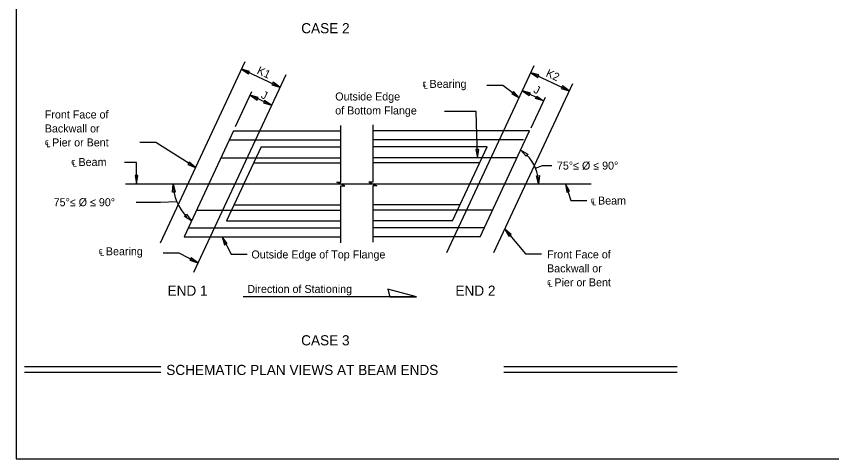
# Model space of a CAD drawing. Extents: x 120790.7 to 120844.8, y 120612.1 to 120653.6.
# Drawn here: x 120790.7 to 120806.1, y 120630.85 to 120639.21 of the extents above; entities that cross this region are included whole.
import ezdxf

# ---------------------------------------------------------------- set-up
doc = ezdxf.new("R2010")
doc.units = 0
for name, color, linetype in [('ActivePts-ConstElements', 7, 'Continuous'), ('AdhocPoint_dp', 7, 'Continuous'), ('Border', 7, 'Continuous'), ('Patterning', 7, 'Continuous'), ('PlotBorder_dp', 7, 'Continuous'), ('TextMisc', 7, 'Continuous')]:
    doc.layers.add(name, color=color, linetype=linetype)

# ---------------------------------------------------------------- blocks, each defined once
blk = doc.blocks.new('Terminator-Arrow')
at = {"layer": 'PlotBorder_dp'}
blk.add_lwpolyline([(0, 0), (-0.00041, 0.000069), (-0.00041, -0.000069)], close=True, dxfattribs=at)

msp = doc.modelspace()

# ---------------------------------------------------------------- linework, layer by layer
at = {"layer": 'ActivePts-ConstElements'}
msp.add_lwpolyline([(120790.703, 120630.851), (120821.491, 120630.851), (120821.491, 120650.31), (120790.703, 120650.31)], close=True, dxfattribs=at)
at = {"layer": 'AdhocPoint_dp'}
for p, q in [((120794.803, 120637.044), (120793.871, 120635.044)), ((120794.803, 120637.044), (120796.83, 120637.044)), ((120800.393, 120637.044), (120797.434, 120637.044)), ((120799.461, 120635.044), (120800.393, 120637.044)), ((120795.324, 120636.742), (120794.673, 120635.346)), ((120795.324, 120636.742), (120796.83, 120636.742)), ((120799.591, 120636.742), (120797.434, 120636.742)), ((120798.94, 120635.346), (120799.591, 120636.742)), ((120795.183, 120636.439), (120796.83, 120636.439)), ((120799.449, 120636.439), (120797.434, 120636.439)), ((120794.815, 120635.649), (120796.83, 120635.649)), ((120799.081, 120635.649), (120797.434, 120635.649)), ((120794.673, 120635.346), (120796.83, 120635.346)), ((120798.94, 120635.346), (120797.434, 120635.346)), ((120793.871, 120635.044), (120796.83, 120635.044)), ((120799.461, 120635.044), (120797.434, 120635.044))]:
    msp.add_line(p, q, dxfattribs=at)
at = {"layer": 'Border'}
for p, q in [((120794.724, 120636.874), (120796.83, 120636.874)), ((120800.277, 120636.874), (120797.434, 120636.874)), ((120794.568, 120636.539), (120796.83, 120636.539)), ((120800.158, 120636.539), (120797.434, 120636.539)), ((120794.106, 120635.549), (120796.83, 120635.549)), ((120799.696, 120635.549), (120797.434, 120635.549)), ((120793.95, 120635.214), (120796.83, 120635.214)), ((120799.54, 120635.214), (120797.434, 120635.214))]:
    msp.add_line(p, q, dxfattribs=at)
at = {"layer": 'Patterning'}
msp.add_lwpolyline([(120797.719, 120634.055), (120797.754, 120633.911), (120798.261, 120633.911)], close=True, dxfattribs=at)
at = {"layer": 'PlotBorder_dp'}
for p, q in [((120795.68, 120637.874), (120794.954, 120638.213)), ((120795.68, 120637.874), (120794.954, 120638.213)), ((120801.143, 120637.805), (120800.416, 120638.144)), ((120801.143, 120637.805), (120800.416, 120638.144)), ((120799.888, 120637.905), (120799.586, 120637.905)), ((120799.888, 120637.905), (120799.586, 120637.905)), ((120800.196, 120637.673), (120799.888, 120637.905)), ((120800.196, 120637.673), (120799.888, 120637.905)), ((120800.659, 120637.614), (120800.257, 120637.802)), ((120800.659, 120637.614), (120800.257, 120637.802)), ((120794.843, 120637.129), (120795.15, 120637.788)), ((120794.843, 120637.129), (120795.15, 120637.788)), ((120795.521, 120637.532), (120795.118, 120637.719)), ((120795.521, 120637.532), (120795.118, 120637.719)), ((120800.421, 120637.104), (120800.691, 120637.683)), ((120800.421, 120637.104), (120800.691, 120637.683)), ((120799.383, 120637.412), (120798.784, 120637.412)), ((120799.383, 120637.412), (120798.784, 120637.412)), ((120799.412, 120636.539), (120799.383, 120637.412)), ((120799.412, 120636.539), (120799.383, 120637.412)), ((120793.336, 120636.826), (120793.034, 120636.826)), ((120793.336, 120636.826), (120793.034, 120636.826)), ((120794.086, 120636.351), (120793.336, 120636.826)), ((120794.086, 120636.351), (120793.336, 120636.826)), ((120792.971, 120636.446), (120792.748, 120636.446)), ((120792.971, 120636.446), (120792.748, 120636.446)), ((120792.973, 120636.044), (120792.97, 120636.446)), ((120792.973, 120636.044), (120792.97, 120636.446)), ((120801.073, 120636.044), (120801.174, 120635.73)), ((120801.073, 120636.044), (120801.174, 120635.73)), ((120801.174, 120635.73), (120801.476, 120635.73)), ((120801.174, 120635.73), (120801.476, 120635.73)), ((120799.923, 120635.19), (120800.316, 120634.723)), ((120799.923, 120635.19), (120800.316, 120634.723)), ((120794.587, 120635.044), (120794.761, 120634.714)), ((120794.587, 120635.044), (120794.761, 120634.714)), ((120793.778, 120634.736), (120793.475, 120634.736)), ((120793.778, 120634.736), (120793.475, 120634.736)), ((120794.131, 120634.552), (120793.778, 120634.736)), ((120794.131, 120634.552), (120793.778, 120634.736)), ((120794.761, 120634.714), (120795.063, 120634.714)), ((120794.761, 120634.714), (120795.063, 120634.714)), ((120800.316, 120634.723), (120800.618, 120634.723)), ((120800.316, 120634.723), (120800.618, 120634.723)), ((120798.261, 120633.911), (120794.986, 120633.911)), ((120793.429, 120632.586), (120790.859, 120632.586)), ((120803.182, 120632.586), (120799.905, 120632.586)), ((120793.429, 120632.478), (120790.859, 120632.478)), ((120803.182, 120632.478), (120799.905, 120632.478))]:
    msp.add_line(p, q, dxfattribs=at)
for points in [[(120800.659, 120637.614), (120800.506, 120637.656), (120800.529, 120637.704)], [(120800.659, 120637.614), (120800.506, 120637.656), (120800.529, 120637.704)], [(120800.617, 120637.634), (120800.515, 120637.663), (120800.529, 120637.693)], [(120800.617, 120637.634), (120800.515, 120637.663), (120800.529, 120637.693)], [(120800.579, 120637.652), (120800.526, 120637.666), (120800.534, 120637.682)], [(120800.579, 120637.652), (120800.526, 120637.666), (120800.534, 120637.682)], [(120800.226, 120636.684), (120800.363, 120636.605), (120800.329, 120636.565)], [(120800.564, 120636.044), (120800.526, 120636.198), (120800.579, 120636.202)], [(120793.665, 120636.044), (120793.703, 120635.89), (120793.65, 120635.886)], [(120794.01, 120635.344), (120793.877, 120635.43), (120793.913, 120635.469)]]:
    msp.add_lwpolyline(points, close=True, dxfattribs=at)
for points in [[(120796.83, 120634.927), (120796.83, 120636.01), (120796.907, 120636.01), (120796.752, 120636.078), (120796.83, 120636.078), (120796.83, 120637.147)], [(120796.83, 120634.927), (120796.83, 120636.01), (120796.907, 120636.01), (120796.752, 120636.078), (120796.83, 120636.078), (120796.83, 120637.147)], [(120797.434, 120637.161), (120797.434, 120636.078), (120797.357, 120636.078), (120797.512, 120636.01), (120797.434, 120636.01), (120797.434, 120634.941)], [(120797.434, 120637.161), (120797.434, 120636.078), (120797.357, 120636.078), (120797.512, 120636.01), (120797.434, 120636.01), (120797.434, 120634.941)], [(120800.505, 120636.34), (120800.635, 120636.394), (120800.814, 120636.394)], [(120793.732, 120635.706), (120793.424, 120635.692), (120792.965, 120635.692)]]:
    msp.add_lwpolyline(points, dxfattribs=at)
for centre, radius, start, end in [((120799.79, 120636.044), 0.774, 0, 44.9892), ((120794.549, 120636.044), 0.884, 180, 224.9892)]:
    msp.add_arc(centre, radius, start, end, dxfattribs=at)
at = {"layer": 'TextMisc'}
for p, q in [((120795.018, 120638.35), (120793.42, 120634.923)), ((120798.832, 120634.746), (120800.48, 120638.281)), ((120795.789, 120638.107), (120794.047, 120634.371)), ((120799.716, 120634.746), (120801.207, 120637.942)), ((120792.766, 120636.044), (120801.553, 120636.044))]:
    msp.add_line(p, q, dxfattribs=at)

# ---------------------------------------------------------------- block references
at = {"layer": 'PlotBorder_dp'}
for p, xscale, yscale, rotation in [((120794.954, 120638.212), 381, 384.0238095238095, 155.0055241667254), ((120794.954, 120638.212), 381, 384.0238095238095, 155.0055241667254), ((120800.416, 120638.144), 381, 384.0238095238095, 155.00552416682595), ((120800.416, 120638.144), 381, 384.0238095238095, 155.00552416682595), ((120795.68, 120637.874), 381, 384.0238095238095, -24.994475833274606), ((120795.68, 120637.874), 381, 384.0238095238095, -24.994475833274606), ((120800.257, 120637.802), 381.00000000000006, 384.0238095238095, 155.00552416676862), ((120800.257, 120637.802), 381.00000000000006, 384.0238095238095, 155.00552416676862), ((120801.143, 120637.805), 381, 384.0238095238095, -24.994475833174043), ((120801.143, 120637.805), 381, 384.0238095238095, -24.994475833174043), ((120795.118, 120637.719), 381, 384.0238095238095, 155.0055241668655), ((120795.118, 120637.719), 381, 384.0238095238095, 155.0055241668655), ((120800.196, 120637.673), 381, 384.0238095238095, -36.99636030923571), ((120800.196, 120637.673), 381, 384.0238095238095, -36.99636030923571), ((120795.521, 120637.531), 381, 384.0238095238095, -24.99447583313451), ((120795.521, 120637.531), 381, 384.0238095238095, -24.99447583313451), ((120799.412, 120636.539), 380.99999999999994, 384.0238095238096, -88.11192467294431), ((120799.412, 120636.539), 380.99999999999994, 384.0238095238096, -88.11192467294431), ((120794.086, 120636.351), 381.00000000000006, 384.0238095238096, -32.331988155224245), ((120794.086, 120636.351), 381.00000000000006, 384.0238095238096, -32.331988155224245), ((120792.973, 120636.044), 380.99999999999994, 384.02380952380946, -89.68002689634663), ((120792.973, 120636.044), 380.99999999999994, 384.02380952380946, -89.68002689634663), ((120801.073, 120636.044), 381, 384.0238095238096, 107.77364180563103), ((120801.073, 120636.044), 381, 384.0238095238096, 107.77364180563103), ((120799.923, 120635.19), 381, 384.0238095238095, 130.02223544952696), ((120799.923, 120635.19), 381, 384.0238095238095, 130.02223544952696), ((120794.587, 120635.044), 381, 384.0238095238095, 117.72534965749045), ((120794.587, 120635.044), 381, 384.0238095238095, 117.72534965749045), ((120794.131, 120634.552), 381, 384.0238095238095, -27.50080843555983), ((120794.131, 120634.552), 381, 384.0238095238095, -27.50080843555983)]:
    msp.add_blockref('Terminator-Arrow', p, dxfattribs=dict(at, xscale=xscale, yscale=yscale, rotation=rotation))

# ---------------------------------------------------------------- texts
at = {"layer": 'Patterning'}
for s, height, p in [('CASE 2', 0.192, (120796.082, 120638.89)), ('℄ Bearing', 0.1512, (120798.367, 120637.859)), ('Outside Edge', 0.1512, (120796.724, 120637.62)), ('of Bottom Flange', 0.1512, (120796.724, 120637.356)), ('℄ Beam', 0.1512, (120791.739, 120636.382)), ('75°≤ Ø ≤ 90°', 0.1512, (120800.909, 120636.314)), ('℄ Beam', 0.1512, (120801.547, 120635.653)), ('75°≤ Ø ≤ 90°', 0.1512, (120791.408, 120635.622)), ('℄ Bearing', 0.1512, (120792.256, 120634.695)), ('Outside Edge of Top Flange', 0.1512, (120795.142, 120634.635)), ('END 1', 0.192, (120793.558, 120633.93)), ('Direction of Stationing', 0.1512, (120795.064, 120633.983)), ('END 2', 0.192, (120798.993, 120633.93)), ('CASE 3', 0.192, (120796.081, 120632.992)), ('SCHEMATIC PLAN VIEWS AT BEAM ENDS', 0.192, (120793.534, 120632.432))]:
    msp.add_text(s, height=height, dxfattribs=at).set_placement(p)
for s, height, p in [('K1', 0.1512, (120795.233, 120638.134)), ('K2', 0.1512, (120800.688, 120638.084)), ('J', 0.151, (120795.309, 120637.675)), ('J', 0.151, (120800.455, 120637.775))]:
    msp.add_text(s, height=height, rotation=335.0055, dxfattribs=at).set_placement(p)
at = {"layer": 'PlotBorder_dp'}
for s, p in [('Front Face of', (120791.241, 120637.28)), ('Backwall or', (120791.241, 120637.016)), ('℄ Pier or Bent', (120791.241, 120636.752)), ('Front Face of', (120800.723, 120634.636)), ('Backwall or', (120800.723, 120634.372)), ('℄ Pier or Bent', (120800.723, 120634.108))]:
    msp.add_text(s, height=0.1512, dxfattribs=at).set_placement(p)

doc.saveas('drawing.dxf')
